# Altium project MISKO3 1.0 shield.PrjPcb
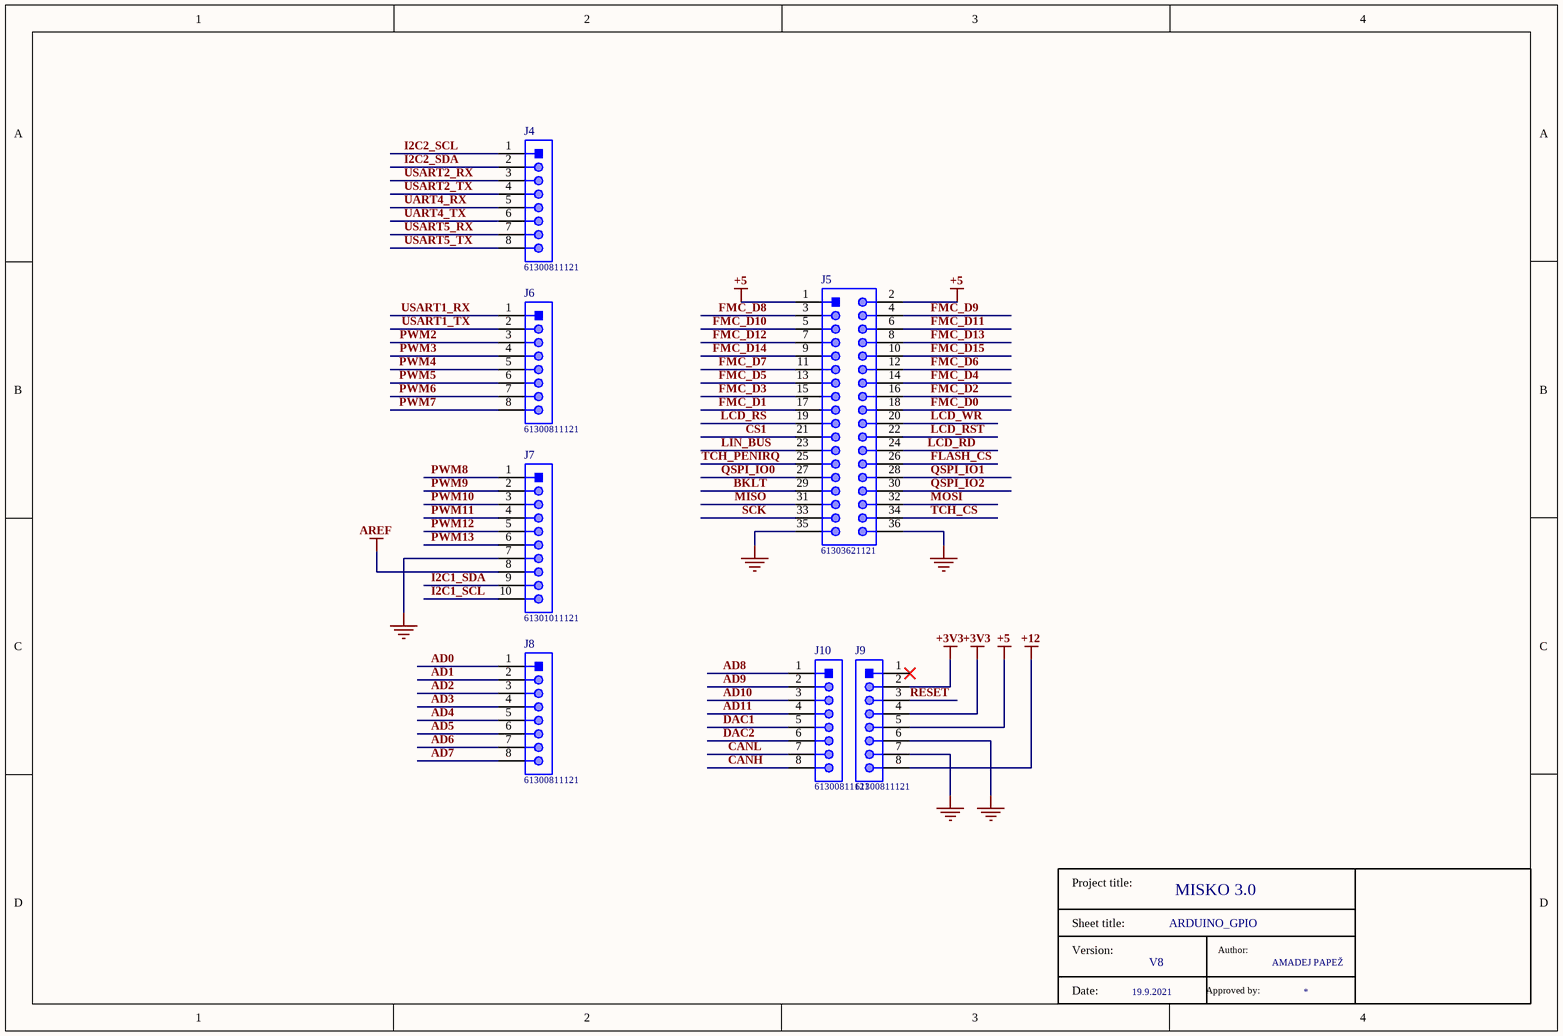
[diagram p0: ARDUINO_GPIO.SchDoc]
1 sheet, 8 parts. Net scope: hierarchical (ports join the sheet entries above them; power ports are global).
Board file: Misko 3 1.0 shield.PcbDoc

## Sheet ARDUINO_GPIO.SchDoc: MISKO 3.0
size A4; Date: 19.9.2021; Author: AMADEJ PAPEŽ; SheetNumber: 1; SheetTotal: 1; Version: V8; SheetTitle: ARDUINO_GPIO

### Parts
J4  61300811121  [61300811121]
J5  61303621121  [61303621121]
J6  61300811121  [61300811121]
J7  61301011121  [61301011121]
J8  61300811121  [61300811121]
J9  61300811121  [61300811121]
J10  61300811121  [61300811121]
T6  (no value)

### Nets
+3V3: J9.2 J9.4
+5: J5.1 J5.2 J9.5
+12: J9.8
AREF: J7.8
GND: J5.35 J5.36 J7.7 J9.6 J9.7
AD0: J8.1  [project net AD0_1]
AD1: J8.2  [project net AD1_1]
AD2: J8.3  [project net AD2_1]
AD3: J8.4  [project net AD3_1]
AD4: J8.5  [project net AD4_1]
AD5: J8.6  [project net AD5_1]
AD6: J8.7  [project net AD6_1]
AD7: J8.8  [project net AD7_1]
AD8: J10.1  [project net AD8_1]
AD9: J10.2  [project net AD9_1]
AD10: J10.3  [project net AD10_1]
AD11: J10.4  [project net AD11_1]
BKLT: J5.29  [project net BKLT_1]
CANH: J10.8  [project net CANH_1]
CANL: J10.7  [project net CANL_1]
CS1: J5.21  [project net CS1_1]
DAC1: J10.5  [project net DAC1_1]
DAC2: J10.6  [project net DAC2_1]
FLASH_CS: J5.26  [project net FLASH_CS_1]
FMC_D0: J5.18  [project net FMC_D0_1]
FMC_D1: J5.17  [project net FMC_D1_1]
FMC_D2: J5.16  [project net FMC_D2_1]
FMC_D3: J5.15  [project net FMC_D3_1]
FMC_D4: J5.14  [project net FMC_D4_1]
FMC_D5: J5.13  [project net FMC_D5_1]
FMC_D6: J5.12  [project net FMC_D6_1]
FMC_D7: J5.11  [project net FMC_D7_1]
FMC_D8: J5.3  [project net FMC_D8_1]
FMC_D9: J5.4  [project net FMC_D9_1]
FMC_D10: J5.5  [project net FMC_D10_1]
FMC_D11: J5.6  [project net FMC_D11_1]
FMC_D12: J5.7  [project net FMC_D12_1]
FMC_D13: J5.8  [project net FMC_D13_1]
FMC_D14: J5.9  [project net FMC_D14_1]
FMC_D15: J5.10  [project net FMC_D15_1]
I2C1_SCL: J7.10  [project net I2C1_SCL_1]
I2C1_SDA: J7.9  [project net I2C1_SDA_1]
I2C2_SCL: J4.1  [project net I2C2_SCL_1]
I2C2_SDA: J4.2  [project net I2C2_SDA_1]
LCD_RD: J5.24  [project net LCD_RD_1]
LCD_RS: J5.19  [project net LCD_RS_1]
LCD_RST: J5.22  [project net LCD_RST_1]
LCD_WR: J5.20  [project net LCD_WR_1]
LIN_BUS: J5.23  [project net LIN_BUS_1]
MISO: J5.31  [project net MISO_1]
MOSI: J5.32  [project net MOSI_1]
PWM2: J6.3  [project net PWM2_1]
PWM3: J6.4  [project net PWM3_1]
PWM4: J6.5  [project net PWM4_1]
PWM5: J6.6  [project net PWM5_1]
PWM6: J6.7  [project net PWM6_1]
PWM7: J6.8  [project net PWM7_1]
PWM8: J7.1  [project net PWM8_1]
PWM9: J7.2  [project net PWM9_1]
PWM10: J7.3  [project net PWM10_1]
PWM11: J7.4  [project net PWM11_1]
PWM12: J7.5  [project net PWM12_1]
PWM13: J7.6  [project net PWM13_1]
QSPI_IO0: J5.27  [project net QSPI_IO0_1]
QSPI_IO1: J5.28  [project net QSPI_IO1_1]
QSPI_IO2: J5.30  [project net QSPI_IO2_1]
RESET: J9.3  [project net RESET_1]
SCK: J5.33  [project net SCK_1]
TCH_CS: J5.34  [project net TCH_CS_1]
TCH_PENIRQ: J5.25  [project net TCH_PENIRQ_1]
UART4_RX: J4.5  [project net UART4_RX_1]
UART4_TX: J4.6  [project net UART4_TX_1]
USART1_RX: J6.1  [project net USART1_RX_1]
USART1_TX: J6.2  [project net USART1_TX_1]
USART2_RX: J4.3  [project net USART2_RX_1]
USART2_TX: J4.4  [project net USART2_TX_1]
USART5_RX: J4.7  [project net USART5_RX_1]
USART5_TX: J4.8  [project net USART5_TX_1]

Not connected (* = marked no-connect by the designer): J9 1*

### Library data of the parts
J4 J6 J8-J10 = CMP-1502-01076-1: THT Vertical Pin Header WR-PHD, Pitch 2.54 mm, Single Row, 8 pins; Manufacturer: Wurth Elektronik; Rated Current: 3A; Pin Number: 8; Working Voltage: 250VAC; Gender: Male; Contact Resistance: 20mOhm; Pitch: 2.54mm; Withstanding Voltage: 500VAC
J5 = CMP-1502-01131-1: THT Vertical Pin Header WR-PHD, Pitch 2.54 mm, Dual Row, 36 pins; Manufacturer: Wurth Elektronik; Gender: Male; Working Voltage: 250VAC; Pin Number: 36; Pitch: 2.54mm; Contact Resistance: 20mOhm; Rated Current: 3A; Withstanding Voltage: 500VAC
J7 = CMP-1502-01082-1: THT Vertical Pin Header WR-PHD, Pitch 2.54 mm, Single Row, 10 pins; Manufacturer: Wurth Elektronik; Contact Resistance: 20mOhm; Rated Current: 3A; Pitch: 2.54mm; Gender: Male; Pin Number: 10; Working Voltage: 250VAC; Withstanding Voltage: 500VAC
T6 = Title block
